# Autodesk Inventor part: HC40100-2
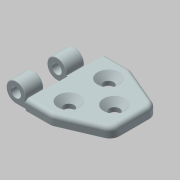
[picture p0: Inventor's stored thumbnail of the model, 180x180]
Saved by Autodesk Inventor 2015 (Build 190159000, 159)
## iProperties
Created: 2014-10
Part Number: HC40100-2
Material: Generic
Document SubType Name: Modeling
Designer: CH.J
Density: 1 g/cm^3
Appearance: 기본값
Author: CH.J
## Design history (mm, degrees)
sketch "스케치8"
  geometry: L1 (4.975, 0)-(39.75, 0); L2 (39.75, 0)-(39.75, 5); L3 (39.75, 5)-(4.975, 5); L4 (4.975, 5)-(4.975, 0); L5 (0, 0.5)-(4.975, 0.5); C1 r 2.5 at (0, 5.5); A1 r 5 centre (0, 5.5) between (4.975, 5) and (0, 0.5); 1 further point
  constraints: 10 end point, 2 centre point, 2 parallel, 2 perpendicular, 2 point on circle, 1 coincident, 1 horizontal, 1 point on line, 1 tangent, 1 vertical alignment
  dimensions: "d76" = 10 diameter of A1; "d78" = 5 distance of L2.end L1.end; "d79" = 39.75 distance from line of L2 point (0, 0); "d80" = 10.5 dimension on A1 L1; "d81" = 5 diameter of C1
extrude "돌출7" new body sketch "스케치8" stored distance "d82" = 40; taper "d83" = 0 deg
sketch "스케치9"
  geometry: L1 (0, 0)-(0, 40) reference; L2 (34.775, 0)-(0, 0) reference; L3 (34.775, 40)-(34.775, 0) reference; L4 (0, 40)-(34.775, 40) reference; L5 (-4.975, 40)-(13.025, 40); L6 (34.775, 40)-(0, 40) reference; L7 (34.775, 9.25)-(34.775, 30.75); L8 (34.775, 30.75)-(13.025, 40); L9 (-4.975, 0)-(13.025, 0); L10 (-4.975, 0)-(-4.975, 40); L11 (-4.975, 0)-(0, 0) reference; L12 (34.775, 9.25)-(13.025, 0); L13 (13.025, 40)-(34.775, 40); L14 (34.775, 30.75)-(34.775, 40); L15 (34.775, 9.25)-(34.775, 0); L16 (34.775, 0)-(13.025, 0); 2 further points
  constraints: 20 end point, 2 collinear, 2 midpoint, 2 perpendicular, 2 point on line, 2 vertical
  dimensions: "d84" = 18 distance of L5.start L5.end; "d85" = 21.5 distance of L7.start L7.end
extrude "돌출8" cut sketch "스케치9" stored distance "d86" = 40; taper "d87" = 0 deg
fillet "모깎기5" dims "d88" = 5
sketch "스케치10"
  geometry: L1 (0, 0)-(0, 40) reference; L2 (-4.975, 40)-(0, 40) reference; L3 (-4.975, 0)-(-4.975, 40) reference; L4 (0, 0)-(-4.975, 0) reference; L5 (-15.967, 0)-(0.525, 0); L6 (0.525, 0)-(0.525, 10.4); L7 (0.525, 10.4)-(-15.967, 10.4); L8 (-15.967, 10.4)-(-15.967, 0); L9 (0.525, 10.4)-(-15.967, 10.4); L10 (-15.967, 10.4)-(-15.967, 19.4); L11 (-15.967, 19.4)-(0.525, 19.4); L12 (0.525, 19.4)-(0.525, 10.4); L13 (0.525, 19.4)-(-15.967, 19.4); L14 (-15.967, 19.4)-(-15.967, 31); L15 (-15.967, 31)-(0.525, 31); L16 (0.525, 31)-(0.525, 19.4); L17 (0.525, 31)-(-17.163, 31); L18 (-17.163, 31)-(-17.163, 40); L19 (-17.163, 40)-(0.525, 40); L20 (0.525, 40)-(0.525, 31)
  constraints: 32 end point, 8 parallel, 4 horizontal, 4 perpendicular, 1 point on line
  dimensions: "d95" = 5.5 distance between parallel lines of L3 L6; "d96" = 10.4 distance of L7.end L5.start; "d97" = 9 distance of L9.end L10.end; "d98" = 11.6 distance of L13.end L14.end; "d99" = 9 distance of L17.end L18.end
extrude "돌출9" cut sketch "스케치10" distance "d93" = 40; taper "d94" = 0 deg
sketch "스케치11"
  geometry: L1 (11.775, 10)-(24.775, 10); L2 (24.775, 10)-(24.775, 30); L3 (24.775, 30)-(11.775, 30); L4 (11.775, 30)-(11.775, 10); L5 (34.775, 27.443)-(34.775, 12.557) reference; 6 further points
  constraints: 8 end point, 3 coincident, 2 midpoint, 2 parallel, 1 horizontal, 1 horizontal alignment, 1 perpendicular
  dimensions: "d100" = 13 distance of L3.end L2.end; "d101" = 20 distance of L2.end L1.end; "d102" = 10 distance between parallel lines of L5 L2
hole "구멍3" sketch "스케치11" at (11.775, 30), (11.775, 10), (24.775, 20) diameter "d103" = 5.2; stored, may be unused: countersink angle "d107" = 90 deg, drill point angle "d109" = 118 deg; dims "d104" = 6, "d105" = 11, "d106" = 2, "d108" = 8
fillet "모깎기6" dims "d110" = 2
fillet "모깎기7" dims "d111" = 0.5
node "솔리드3"
node "투영된 루프2"
node "투영된 루프3"
